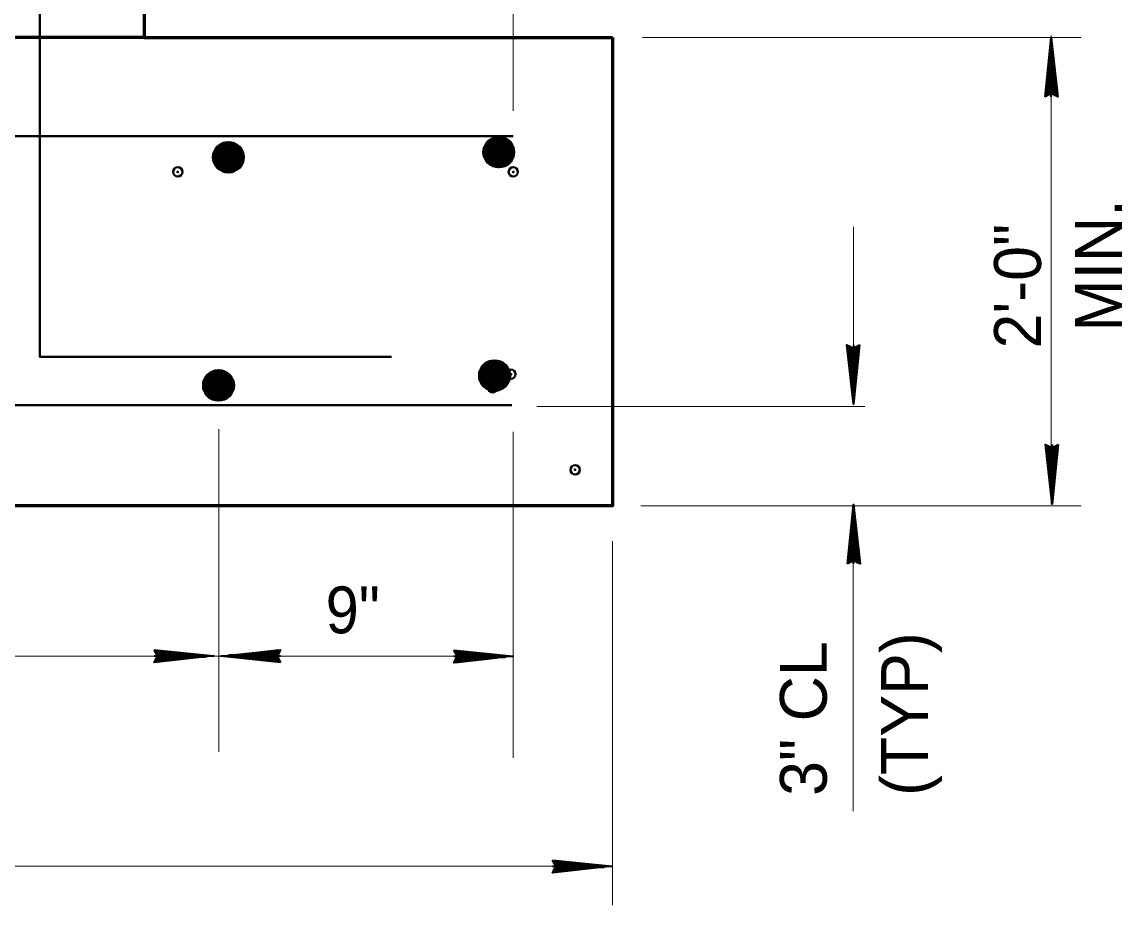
# Model space of a CAD drawing. Extents: x 14.14 to 17.34, y -1.61 to 0.38.
# Drawn here: x 15.7348 to 15.9304, y -0.0862 to 0.0709 of the extents above; entities that cross this region are included whole.
import ezdxf
from ezdxf.enums import TextEntityAlignment as Align

# ---------------------------------------------------------------- set-up
doc = ezdxf.new("R2010")
doc.units = 0
doc.header["$LTSCALE"] = 0.0033
doc.header["$PDMODE"] = 32
doc.header["$PDSIZE"] = 0.00165
doc.layers.add('1', color=7, linetype='Continuous', lineweight=40)

msp = doc.modelspace()

# ---------------------------------------------------------------- linework, layer by layer
at = {"layer": '1', "lineweight": 13}
for p, q in [((15.822167, 0.055083), (15.822167, 0.113)), ((15.917833, 0.0685), (15.917833, -0.014833)), ((15.845167, 0.068167), (15.923167, 0.068167)), ((15.882667, 0.003167), (15.882667, 0.0345)), ((15.826333, 0.0025), (15.884667, 0.0025)), ((15.769833, -0.0015), (15.769833, -0.058917)), ((15.822167, -0.002), (15.822167, -0.06)), ((15.844833, -0.015167), (15.923167, -0.015167)), ((15.923167, -0.015167), (15.846417, -0.015167)), ((15.839833, -0.021417), (15.839833, -0.086167)), ((15.882583, -0.0695), (15.882583, -0.022583)), ((15.523583, -0.041917), (15.820833, -0.041917)), ((15.511083, -0.07925), (15.837333, -0.07925))]:
    msp.add_line(p, q, dxfattribs=at)
at = {"layer": '1', "lineweight": 60}
for p, q in [((15.7565, 0.068167), (15.694, 0.068167)), ((15.81775, 0.049333), (15.817583, 0.046417)), ((15.818, 0.049333), (15.81775, 0.046417)), ((15.818167, 0.049333), (15.818, 0.046333)), ((15.818333, 0.049333), (15.818083, 0.046333)), ((15.8185, 0.049333), (15.818333, 0.046333)), ((15.81875, 0.049333), (15.818583, 0.046333)), ((15.819, 0.049333), (15.81875, 0.046333)), ((15.819083, 0.04925), (15.818917, 0.046333)), ((15.81925, 0.04925), (15.819083, 0.046333)), ((15.819417, 0.04925), (15.81925, 0.046333)), ((15.819667, 0.04925), (15.819417, 0.046333)), ((15.819833, 0.04925), (15.819667, 0.046333)), ((15.820083, 0.049167), (15.819833, 0.04625)), ((15.820333, 0.049167), (15.820083, 0.04625)), ((15.8205, 0.049167), (15.820333, 0.04625)), ((15.820583, 0.049167), (15.820417, 0.04625)), ((15.82075, 0.049167), (15.820583, 0.04625)), ((15.820833, 0.049167), (15.820667, 0.04625)), ((15.821083, 0.049083), (15.820833, 0.046167)), ((15.82125, 0.049083), (15.821083, 0.046167)), ((15.821417, 0.049083), (15.821167, 0.046167)), ((15.821583, 0.049083), (15.821417, 0.046167)), ((15.821833, 0.049083), (15.821667, 0.046167)), ((15.822083, 0.047167), (15.821917, 0.049)), ((15.769667, 0.048417), (15.7695, 0.0455)), ((15.769917, 0.048417), (15.769667, 0.0455)), ((15.770083, 0.048417), (15.769917, 0.045417)), ((15.77025, 0.048417), (15.77, 0.045417)), ((15.770417, 0.048417), (15.77025, 0.045417)), ((15.770667, 0.048417), (15.7705, 0.045417)), ((15.770917, 0.048417), (15.770667, 0.045417)), ((15.771, 0.048333), (15.770833, 0.045417)), ((15.771167, 0.048333), (15.771, 0.045417)), ((15.771333, 0.048333), (15.771167, 0.045417)), ((15.771583, 0.048333), (15.771333, 0.045417)), ((15.77175, 0.048333), (15.771583, 0.045417)), ((15.772, 0.04825), (15.77175, 0.045333)), ((15.77225, 0.04825), (15.772, 0.045333)), ((15.772417, 0.04825), (15.77225, 0.045333)), ((15.7725, 0.04825), (15.772333, 0.045333)), ((15.772667, 0.04825), (15.7725, 0.045333)), ((15.77275, 0.04825), (15.772583, 0.045333)), ((15.773, 0.048167), (15.77275, 0.04525)), ((15.773167, 0.048167), (15.773, 0.04525)), ((15.773333, 0.048167), (15.773083, 0.04525)), ((15.7735, 0.048167), (15.773333, 0.04525)), ((15.77375, 0.048167), (15.773583, 0.04525)), ((15.774, 0.04625), (15.773833, 0.048083)), ((15.822083, 0.047167), (15.817333, 0.046417)), ((15.774, 0.04625), (15.76925, 0.0455)), ((15.767917, 0.007833), (15.76775, 0.004917)), ((15.768167, 0.007833), (15.767917, 0.004917)), ((15.768333, 0.007833), (15.768167, 0.004833)), ((15.7685, 0.007833), (15.76825, 0.004833)), ((15.768667, 0.007833), (15.7685, 0.004833)), ((15.768917, 0.007833), (15.76875, 0.004833)), ((15.769167, 0.007833), (15.768917, 0.004833)), ((15.817, 0.009583), (15.816833, 0.006667)), ((15.81725, 0.009583), (15.817, 0.006667)), ((15.817417, 0.009583), (15.81725, 0.006583)), ((15.817583, 0.009583), (15.817333, 0.006583)), ((15.81775, 0.009583), (15.817583, 0.006583)), ((15.818, 0.009583), (15.817833, 0.006583)), ((15.81825, 0.009583), (15.818, 0.006583)), ((15.818333, 0.0095), (15.818167, 0.006583)), ((15.8185, 0.0095), (15.818333, 0.006583)), ((15.818667, 0.0095), (15.8185, 0.006583)), ((15.818917, 0.0095), (15.818667, 0.006583)), ((15.819083, 0.0095), (15.818917, 0.006583)), ((15.819333, 0.009417), (15.819083, 0.0065)), ((15.819583, 0.009417), (15.819333, 0.0065)), ((15.81975, 0.009417), (15.819583, 0.0065)), ((15.819833, 0.009417), (15.819667, 0.0065)), ((15.82, 0.009417), (15.819833, 0.0065)), ((15.820083, 0.009417), (15.819917, 0.0065)), ((15.820333, 0.009333), (15.820083, 0.006417)), ((15.8205, 0.009333), (15.820333, 0.006417)), ((15.820667, 0.009333), (15.820417, 0.006417)), ((15.820833, 0.009333), (15.820667, 0.006417)), ((15.821083, 0.009333), (15.820917, 0.006417)), ((15.821333, 0.007417), (15.821167, 0.00925)), ((15.76925, 0.00775), (15.769083, 0.004833)), ((15.769417, 0.00775), (15.76925, 0.004833)), ((15.769583, 0.00775), (15.769417, 0.004833)), ((15.769833, 0.00775), (15.769583, 0.004833)), ((15.77, 0.00775), (15.769833, 0.004833)), ((15.77025, 0.007667), (15.77, 0.00475)), ((15.7705, 0.007667), (15.77025, 0.00475)), ((15.770667, 0.007667), (15.7705, 0.00475)), ((15.77075, 0.007667), (15.770583, 0.00475)), ((15.770917, 0.007667), (15.77075, 0.00475)), ((15.771, 0.007667), (15.770833, 0.00475)), ((15.77125, 0.007583), (15.771, 0.004667)), ((15.771417, 0.007583), (15.77125, 0.004667)), ((15.771583, 0.007583), (15.771333, 0.004667)), ((15.77175, 0.007583), (15.771583, 0.004667)), ((15.772, 0.007583), (15.771833, 0.004667)), ((15.77225, 0.005667), (15.772083, 0.0075)), ((15.821333, 0.007417), (15.816583, 0.006667)), ((15.77225, 0.005667), (15.7675, 0.004917))]:
    msp.add_line(p, q, dxfattribs=at)
at = {"layer": '1', "lineweight": 35}
for p, q in [((15.917833, 0.057583), (15.917833, 0.068167)), ((15.916833, 0.057833), (15.91775, 0.065667)), ((15.916833, 0.057833), (15.91775, 0.065667)), ((15.916917, 0.057833), (15.91775, 0.065667)), ((15.917, 0.057833), (15.917833, 0.065667)), ((15.917, 0.057833), (15.918, 0.065667)), ((15.9185, 0.05775), (15.91775, 0.065083)), ((15.918667, 0.057833), (15.917833, 0.065167)), ((15.91875, 0.057833), (15.918, 0.065167)), ((15.918917, 0.057833), (15.918083, 0.065167)), ((15.881583, 0.01325), (15.882417, 0.005917)), ((15.88175, 0.01325), (15.8825, 0.005917)), ((15.881833, 0.01325), (15.882667, 0.005917)), ((15.882, 0.013333), (15.88275, 0.006)), ((15.8835, 0.01325), (15.8825, 0.005417)), ((15.882667, 0.0135), (15.882667, 0.002917)), ((15.8835, 0.01325), (15.882667, 0.005417)), ((15.883667, 0.01325), (15.88275, 0.005417)), ((15.883667, 0.01325), (15.88275, 0.005417)), ((15.883583, 0.01325), (15.88275, 0.005417)), ((15.916917, -0.0045), (15.91775, -0.011833)), ((15.917083, -0.0045), (15.917833, -0.011833)), ((15.917167, -0.0045), (15.918, -0.011833)), ((15.917333, -0.004417), (15.918083, -0.01175)), ((15.918833, -0.0045), (15.917833, -0.012333)), ((15.918, -0.00425), (15.918, -0.014833)), ((15.918833, -0.0045), (15.918, -0.012333)), ((15.919, -0.0045), (15.918083, -0.012333)), ((15.919, -0.0045), (15.918083, -0.012333)), ((15.918917, -0.0045), (15.918083, -0.012333)), ((15.882667, -0.0255), (15.882667, -0.014917)), ((15.881667, -0.02525), (15.882583, -0.017417)), ((15.881667, -0.02525), (15.882583, -0.017417)), ((15.88175, -0.02525), (15.882583, -0.017417)), ((15.881833, -0.02525), (15.882667, -0.017417)), ((15.881833, -0.02525), (15.882833, -0.017417)), ((15.883333, -0.025333), (15.882583, -0.018)), ((15.8835, -0.02525), (15.882667, -0.017917)), ((15.883583, -0.02525), (15.882833, -0.017917)), ((15.88375, -0.02525), (15.882917, -0.017917)), ((15.758583, -0.040833), (15.766417, -0.04175)), ((15.758583, -0.040833), (15.766417, -0.04175)), ((15.758583, -0.040917), (15.766417, -0.04175)), ((15.758583, -0.041), (15.766417, -0.041833)), ((15.758583, -0.041), (15.766417, -0.042)), ((15.7805, -0.040833), (15.773167, -0.041667)), ((15.7805, -0.041), (15.773167, -0.04175)), ((15.811833, -0.040917), (15.819667, -0.041833)), ((15.811833, -0.040917), (15.819667, -0.041833)), ((15.811833, -0.041), (15.819667, -0.041833)), ((15.758333, -0.041833), (15.768917, -0.041833)), ((15.7585, -0.0425), (15.765833, -0.04175)), ((15.758583, -0.042667), (15.765917, -0.041833)), ((15.758583, -0.04275), (15.765917, -0.042)), ((15.758583, -0.042917), (15.765917, -0.042083)), ((15.78075, -0.041917), (15.770167, -0.041917)), ((15.7805, -0.04275), (15.772667, -0.04175)), ((15.7805, -0.04275), (15.772667, -0.041917)), ((15.7805, -0.042917), (15.772667, -0.042)), ((15.7805, -0.042917), (15.772667, -0.042)), ((15.7805, -0.042833), (15.772667, -0.042)), ((15.7805, -0.041083), (15.773167, -0.041917)), ((15.780583, -0.04125), (15.77325, -0.042)), ((15.811583, -0.041917), (15.822167, -0.041917)), ((15.81175, -0.042583), (15.819083, -0.041833)), ((15.811833, -0.041083), (15.819667, -0.041917)), ((15.811833, -0.041083), (15.819667, -0.042083)), ((15.811833, -0.04275), (15.819167, -0.041917)), ((15.811833, -0.042833), (15.819167, -0.042083)), ((15.811833, -0.043), (15.819167, -0.042167)), ((15.829167, -0.07925), (15.83975, -0.07925)), ((15.829333, -0.079917), (15.836667, -0.079167)), ((15.829417, -0.07825), (15.83725, -0.079167)), ((15.829417, -0.07825), (15.83725, -0.079167)), ((15.829417, -0.078333), (15.83725, -0.079167)), ((15.829417, -0.078417), (15.83725, -0.07925)), ((15.829417, -0.078417), (15.83725, -0.079417)), ((15.829417, -0.080083), (15.83675, -0.07925)), ((15.829417, -0.080167), (15.83675, -0.079417)), ((15.829417, -0.080333), (15.83675, -0.0795))]:
    msp.add_line(p, q, dxfattribs=at)
at = {"layer": '1'}
for p, q in [((15.524417, 0.050583), (15.822167, 0.050583)), ((15.77175, 0.047917), (15.773083, 0.048917)), ((15.773833, 0.048083), (15.772583, 0.04925)), ((15.8175, 0.049333), (15.822083, 0.047167)), ((15.81775, 0.048917), (15.821667, 0.048167)), ((15.817833, 0.049333), (15.82175, 0.048667)), ((15.817833, 0.049167), (15.82175, 0.048417)), ((15.817917, 0.049667), (15.82175, 0.049)), ((15.819833, 0.048833), (15.821167, 0.049833)), ((15.821917, 0.049), (15.820667, 0.050167)), ((15.769417, 0.048417), (15.774, 0.04625)), ((15.7695, 0.047), (15.773333, 0.04625)), ((15.769583, 0.047417), (15.773417, 0.04675)), ((15.769583, 0.04725), (15.773417, 0.0465)), ((15.769667, 0.048), (15.773583, 0.04725)), ((15.769667, 0.047833), (15.773583, 0.047083)), ((15.769667, 0.047583), (15.7735, 0.046833)), ((15.76975, 0.048417), (15.773667, 0.04775)), ((15.76975, 0.04825), (15.773667, 0.0475)), ((15.769833, 0.04875), (15.773667, 0.048083)), ((15.817417, 0.047083), (15.821333, 0.046333)), ((15.8175, 0.0475), (15.821417, 0.04675)), ((15.817583, 0.047917), (15.821417, 0.047167)), ((15.817583, 0.04775), (15.821417, 0.047)), ((15.817667, 0.048333), (15.8215, 0.047667)), ((15.817667, 0.048167), (15.8215, 0.047417)), ((15.81775, 0.04875), (15.821667, 0.048)), ((15.81775, 0.0485), (15.821583, 0.04775)), ((15.76925, 0.045667), (15.773083, 0.044917)), ((15.76925, 0.0455), (15.773083, 0.04475)), ((15.769333, 0.046167), (15.77325, 0.045417)), ((15.769333, 0.046), (15.773167, 0.04525)), ((15.769333, 0.04575), (15.773167, 0.045083)), ((15.769417, 0.046583), (15.773333, 0.045833)), ((15.7695, 0.046833), (15.773333, 0.046083)), ((15.773583, 0.04525), (15.769833, 0.044833)), ((15.817333, 0.046583), (15.821167, 0.045833)), ((15.817333, 0.046417), (15.821167, 0.045667)), ((15.817417, 0.046917), (15.82125, 0.046167)), ((15.817417, 0.046667), (15.82125, 0.046)), ((15.821667, 0.046167), (15.817917, 0.04575)), ((15.817167, 0.009917), (15.821, 0.00925)), ((15.819083, 0.009083), (15.820417, 0.010083)), ((15.821167, 0.00925), (15.819917, 0.010417)), ((15.767667, 0.007833), (15.77225, 0.005667)), ((15.768, 0.007833), (15.771917, 0.007167)), ((15.768083, 0.008167), (15.771917, 0.0075)), ((15.77, 0.007333), (15.771333, 0.008333)), ((15.772083, 0.0075), (15.770833, 0.008667)), ((15.81675, 0.009583), (15.821333, 0.007417)), ((15.816833, 0.008167), (15.820667, 0.007417)), ((15.816833, 0.008), (15.820667, 0.00725)), ((15.816917, 0.008583), (15.82075, 0.007917)), ((15.816917, 0.008417), (15.82075, 0.007667)), ((15.817, 0.009167), (15.820917, 0.008417)), ((15.817, 0.009), (15.820917, 0.00825)), ((15.817, 0.00875), (15.820833, 0.008)), ((15.817083, 0.009583), (15.821, 0.008917)), ((15.817083, 0.009417), (15.821, 0.008667)), ((15.767667, 0.006), (15.771583, 0.00525)), ((15.76775, 0.006417), (15.771583, 0.005667)), ((15.76775, 0.00625), (15.771583, 0.0055)), ((15.767833, 0.006833), (15.771667, 0.006167)), ((15.767833, 0.006667), (15.771667, 0.005917)), ((15.767917, 0.007417), (15.771833, 0.006667)), ((15.767917, 0.00725), (15.771833, 0.0065)), ((15.767917, 0.007), (15.77175, 0.00625)), ((15.768, 0.007667), (15.771917, 0.006917)), ((15.816583, 0.006833), (15.820417, 0.006083)), ((15.816583, 0.006667), (15.820417, 0.005917)), ((15.816667, 0.007333), (15.820583, 0.006583)), ((15.816667, 0.007167), (15.8205, 0.006417)), ((15.816667, 0.006917), (15.8205, 0.00625)), ((15.81675, 0.00775), (15.820667, 0.007)), ((15.820917, 0.006417), (15.817167, 0.006)), ((15.7675, 0.005083), (15.771333, 0.004333)), ((15.7675, 0.004917), (15.771333, 0.004167)), ((15.767583, 0.005583), (15.7715, 0.004833)), ((15.767583, 0.005417), (15.771417, 0.004667)), ((15.767583, 0.005167), (15.771417, 0.0045)), ((15.771833, 0.004667), (15.768083, 0.00425)), ((15.52425, 0.00275), (15.821917, 0.00275))]:
    msp.add_line(p, q, dxfattribs=at)
at = {"layer": '1', "lineweight": 60}
for points in [[(15.7565, 0.172333), (15.7565, 0.068167), (15.839833, 0.068167)], [(15.839833, 0.068167), (15.839833, -0.015167), (15.5065, -0.015167)], [(15.773083, 0.04475), (15.773083, 0.048917), (15.771417, 0.04425), (15.771917, 0.049417), (15.769833, 0.044833), (15.770583, 0.049333), (15.772167, 0.044333), (15.769, 0.047667), (15.773833, 0.048083), (15.770583, 0.044417), (15.772583, 0.04925), (15.769417, 0.048417), (15.76925, 0.0455)], [(15.769833, 0.044833), (15.771333, 0.047083), (15.769167, 0.048), (15.771167, 0.049417), (15.771333, 0.047167), (15.773, 0.044833), (15.769, 0.047167), (15.77175, 0.047917)], [(15.772583, 0.04925), (15.771333, 0.047083), (15.773583, 0.04525)], [(15.816917, 0.047667), (15.822083, 0.048333), (15.8175, 0.049333)], [(15.821167, 0.045667), (15.821167, 0.049833), (15.8195, 0.045167), (15.82, 0.050333), (15.817917, 0.04575), (15.818667, 0.05025), (15.82025, 0.04525), (15.817083, 0.048583), (15.821917, 0.049), (15.818667, 0.045333), (15.820667, 0.050167), (15.8175, 0.049333), (15.817333, 0.046417)], [(15.817917, 0.04575), (15.819417, 0.048), (15.81725, 0.048917), (15.81925, 0.050333), (15.819417, 0.048083), (15.821083, 0.04575), (15.817083, 0.048083), (15.819833, 0.048833)], [(15.820667, 0.050167), (15.819417, 0.048), (15.821667, 0.046167)], [(15.768833, 0.04675), (15.774, 0.047417), (15.769417, 0.048417)], [(15.820417, 0.005917), (15.820417, 0.010083), (15.81875, 0.005417), (15.81925, 0.010583), (15.817167, 0.006), (15.817917, 0.0105), (15.8195, 0.0055), (15.816333, 0.008833), (15.821167, 0.00925), (15.817917, 0.005583), (15.819917, 0.010417), (15.81675, 0.009583), (15.816583, 0.006667)], [(15.817167, 0.006), (15.818667, 0.00825), (15.8165, 0.009167), (15.8185, 0.010583), (15.818667, 0.008333), (15.820333, 0.006), (15.816333, 0.008333), (15.819083, 0.009083)], [(15.819917, 0.010417), (15.818667, 0.00825), (15.820917, 0.006417)], [(15.767083, 0.006167), (15.77225, 0.006833), (15.767667, 0.007833)], [(15.771333, 0.004167), (15.771333, 0.008333), (15.769667, 0.003667), (15.770167, 0.008833), (15.768083, 0.00425), (15.768833, 0.00875), (15.770417, 0.00375), (15.76725, 0.007083), (15.772083, 0.0075), (15.768833, 0.003833), (15.770833, 0.008667), (15.767667, 0.007833), (15.7675, 0.004917)], [(15.768083, 0.00425), (15.769583, 0.0065), (15.767417, 0.007417), (15.769417, 0.008833), (15.769583, 0.006583), (15.77125, 0.00425), (15.76725, 0.006583), (15.77, 0.007333)], [(15.770833, 0.008667), (15.769583, 0.0065), (15.771833, 0.004667)], [(15.816167, 0.007917), (15.821333, 0.008583), (15.81675, 0.009583)]]:
    msp.add_lwpolyline(points, dxfattribs=at)
at = {"layer": '1'}
for points in [[(15.738, 0.124333), (15.738, 0.011333), (15.8005, 0.011333)], [(15.817333, 0.046417), (15.819417, 0.045167), (15.821167, 0.045667), (15.822083, 0.047167)], [(15.76925, 0.0455), (15.771333, 0.04425), (15.773083, 0.04475), (15.774, 0.04625)], [(15.816583, 0.006667), (15.818667, 0.005417), (15.820417, 0.005917), (15.821333, 0.007417)], [(15.7675, 0.004917), (15.769583, 0.003667), (15.771333, 0.004167), (15.77225, 0.005667)]]:
    msp.add_lwpolyline(points, dxfattribs=at)
at = {"layer": '1', "lineweight": 35}
for points in [[(15.91675, 0.057583), (15.917833, 0.068167), (15.919, 0.057583), (15.917833, 0.058167)], [(15.91775, 0.058333), (15.917667, 0.063), (15.91775, 0.063), (15.91775, 0.062083), (15.917667, 0.058333), (15.917583, 0.061333), (15.9175, 0.058167), (15.917417, 0.060417), (15.917333, 0.058167), (15.917583, 0.061667), (15.91775, 0.066333), (15.918, 0.065417), (15.918, 0.066667), (15.918, 0.058333), (15.918167, 0.06075), (15.918167, 0.058167), (15.91775, 0.0635), (15.918417, 0.058167)], [(15.88375, 0.0135), (15.882667, 0.002917), (15.8815, 0.0135), (15.882667, 0.012917)], [(15.88275, 0.01275), (15.882833, 0.008083), (15.88275, 0.008083), (15.88275, 0.009), (15.882833, 0.01275), (15.882917, 0.00975), (15.883, 0.012917), (15.883083, 0.010667), (15.883167, 0.012917), (15.882917, 0.009417), (15.88275, 0.00475), (15.8825, 0.005667), (15.8825, 0.004417), (15.8825, 0.01275), (15.882333, 0.010333), (15.882333, 0.012917), (15.88275, 0.007583), (15.882083, 0.012917)], [(15.919083, -0.00425), (15.918, -0.014833), (15.916833, -0.00425), (15.918, -0.004833)], [(15.918083, -0.005), (15.918167, -0.009667), (15.918083, -0.009667), (15.918083, -0.00875), (15.918167, -0.005), (15.91825, -0.008), (15.918333, -0.004833), (15.918417, -0.007083), (15.9185, -0.004833), (15.91825, -0.008333), (15.918083, -0.013), (15.917833, -0.012083), (15.917833, -0.013333), (15.917833, -0.005), (15.917667, -0.007417), (15.917667, -0.004833), (15.918083, -0.010167), (15.917417, -0.004833)], [(15.881583, -0.0255), (15.882667, -0.014917), (15.883833, -0.0255), (15.882667, -0.024917)], [(15.882583, -0.02475), (15.8825, -0.020083), (15.882583, -0.020083), (15.882583, -0.021), (15.8825, -0.02475), (15.882417, -0.02175), (15.882333, -0.024917), (15.88225, -0.022667), (15.882167, -0.024917), (15.882417, -0.021417), (15.882583, -0.01675), (15.882833, -0.017667), (15.882833, -0.016417), (15.882833, -0.02475), (15.883, -0.022333), (15.883, -0.024917), (15.882583, -0.019583), (15.88325, -0.024917)], [(15.758333, -0.04075), (15.768917, -0.041833), (15.758333, -0.043), (15.758917, -0.041833)], [(15.78075, -0.043), (15.770167, -0.041917), (15.78075, -0.04075), (15.780167, -0.041917)], [(15.811583, -0.040833), (15.822167, -0.041917), (15.811583, -0.043083), (15.812167, -0.041917)], [(15.759083, -0.04175), (15.76375, -0.041667), (15.76375, -0.04175), (15.762833, -0.04175), (15.759083, -0.041667), (15.762083, -0.041583), (15.758917, -0.0415), (15.761167, -0.041417), (15.758917, -0.041333), (15.762417, -0.041583), (15.767083, -0.04175), (15.766167, -0.042), (15.767417, -0.042), (15.759083, -0.042), (15.7615, -0.042167), (15.758917, -0.042167), (15.76425, -0.04175), (15.758917, -0.042417)], [(15.78, -0.042), (15.775333, -0.042083), (15.775333, -0.042), (15.77625, -0.042), (15.78, -0.042083), (15.777, -0.042167), (15.780167, -0.04225), (15.777917, -0.042333), (15.780167, -0.042417), (15.776667, -0.042167), (15.772, -0.042), (15.772917, -0.04175), (15.771667, -0.04175), (15.78, -0.04175), (15.777583, -0.041583), (15.780167, -0.041583), (15.774833, -0.042), (15.780167, -0.041333)], [(15.812333, -0.041833), (15.817, -0.04175), (15.817, -0.041833), (15.816083, -0.041833), (15.812333, -0.04175), (15.815333, -0.041667), (15.812167, -0.041583), (15.814417, -0.0415), (15.812167, -0.041417), (15.815667, -0.041667), (15.820333, -0.041833), (15.819417, -0.042083), (15.820667, -0.042083), (15.812333, -0.042083), (15.81475, -0.04225), (15.812167, -0.04225), (15.8175, -0.041833), (15.812167, -0.0425)], [(15.829167, -0.078167), (15.83975, -0.07925), (15.829167, -0.080417), (15.82975, -0.07925)], [(15.829917, -0.079167), (15.834583, -0.079083), (15.834583, -0.079167), (15.833667, -0.079167), (15.829917, -0.079083), (15.832917, -0.079), (15.82975, -0.078917), (15.832, -0.078833), (15.82975, -0.07875), (15.83325, -0.079), (15.837917, -0.079167), (15.837, -0.079417), (15.83825, -0.079417), (15.829917, -0.079417), (15.832333, -0.079583), (15.82975, -0.079583), (15.835083, -0.079167), (15.82975, -0.079833)]]:
    msp.add_lwpolyline(points, close=True, dxfattribs=at)
for points in [[(15.91775, 0.058333), (15.917, 0.057917), (15.91725, 0.058167), (15.917583, 0.058333), (15.9175, 0.058583), (15.917167, 0.058417), (15.917917, 0.05825), (15.918417, 0.058083), (15.918833, 0.057833)], [(15.88275, 0.01275), (15.8835, 0.013167), (15.88325, 0.012917), (15.882917, 0.01275), (15.883, 0.0125), (15.883333, 0.012667), (15.882583, 0.012833), (15.882083, 0.013), (15.881667, 0.01325)], [(15.918083, -0.005), (15.918833, -0.004583), (15.918583, -0.004833), (15.91825, -0.005), (15.918333, -0.00525), (15.918667, -0.005083), (15.917917, -0.004917), (15.917417, -0.00475), (15.917, -0.0045)], [(15.882583, -0.02475), (15.881833, -0.025167), (15.882083, -0.024917), (15.882417, -0.02475), (15.882333, -0.0245), (15.882, -0.024667), (15.88275, -0.024833), (15.88325, -0.025), (15.883667, -0.02525)], [(15.759083, -0.04175), (15.758667, -0.041), (15.758917, -0.04125), (15.759083, -0.041583), (15.759333, -0.0415), (15.759167, -0.041167), (15.759, -0.041917), (15.758833, -0.042417), (15.758583, -0.042833)], [(15.78, -0.042), (15.780417, -0.04275), (15.780167, -0.0425), (15.78, -0.042167), (15.77975, -0.04225), (15.779917, -0.042583), (15.780083, -0.041833), (15.78025, -0.041333), (15.7805, -0.040917)], [(15.812333, -0.041833), (15.811917, -0.041083), (15.812167, -0.041333), (15.812333, -0.041667), (15.812583, -0.041583), (15.812417, -0.04125), (15.81225, -0.042), (15.812083, -0.0425), (15.811833, -0.042917)], [(15.829917, -0.079167), (15.8295, -0.078417), (15.82975, -0.078667), (15.829917, -0.079), (15.830167, -0.078917), (15.83, -0.078583), (15.829833, -0.079333), (15.829667, -0.079833), (15.829417, -0.08025)]]:
    msp.add_lwpolyline(points, dxfattribs=at)
at = {"layer": '1', "lineweight": 60}
for centre in [(15.7715, 0.04685), (15.819583, 0.047767), (15.818833, 0.008017), (15.76975, 0.006267)]:
    msp.add_circle(centre, 0.00264, dxfattribs=at)
at = {"layer": '1'}
for p in [(15.820167, 0.046917), (15.7625, 0.04425), (15.822167, 0.04425), (15.819, 0.007), (15.82175, 0.00825), (15.769667, 0.005583), (15.8185, 0.005833), (15.833167, -0.00875)]:
    msp.add_point(p, dxfattribs=at)

# ---------------------------------------------------------------- texts
for s, height, p in [('MIN.', 0.008334, (15.930417, 0.015833)), ('2\'-0"', 0.008333, (15.916, 0.012833)), ('(TYP)', 0.008334, (15.895917, -0.06675)), ('3" CL', 0.008334, (15.877917, -0.06675))]:
    msp.add_text(s, height=height, rotation=90, dxfattribs=at).set_placement(p)
at = {"layer": '1', "width": 0.95}
msp.add_text('9"', height=0.008334, dxfattribs=at).set_placement((15.793625, -0.037833), align=Align.CENTER)

doc.saveas('drawing.dxf')
